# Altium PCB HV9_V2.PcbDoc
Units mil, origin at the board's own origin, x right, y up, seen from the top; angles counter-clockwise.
Board outline 6000 x 4000 mil, 2 copper layers (顶面, 底面), stack 12.7 mil thick; 1 components, 0 nets, 72 pads, 0 vias.
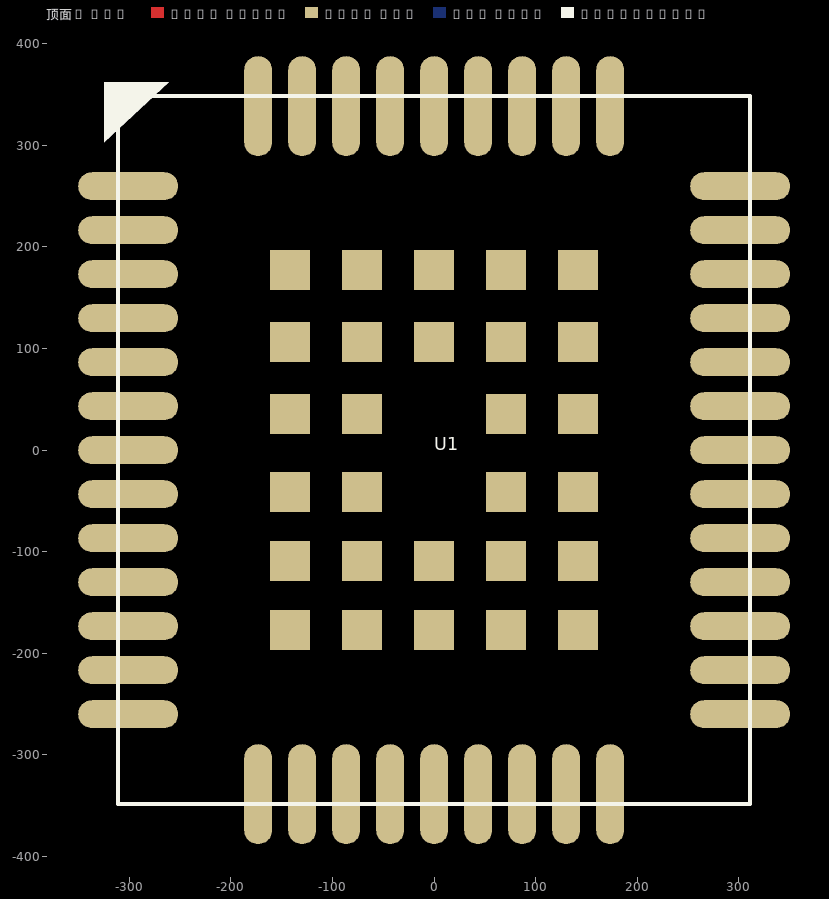
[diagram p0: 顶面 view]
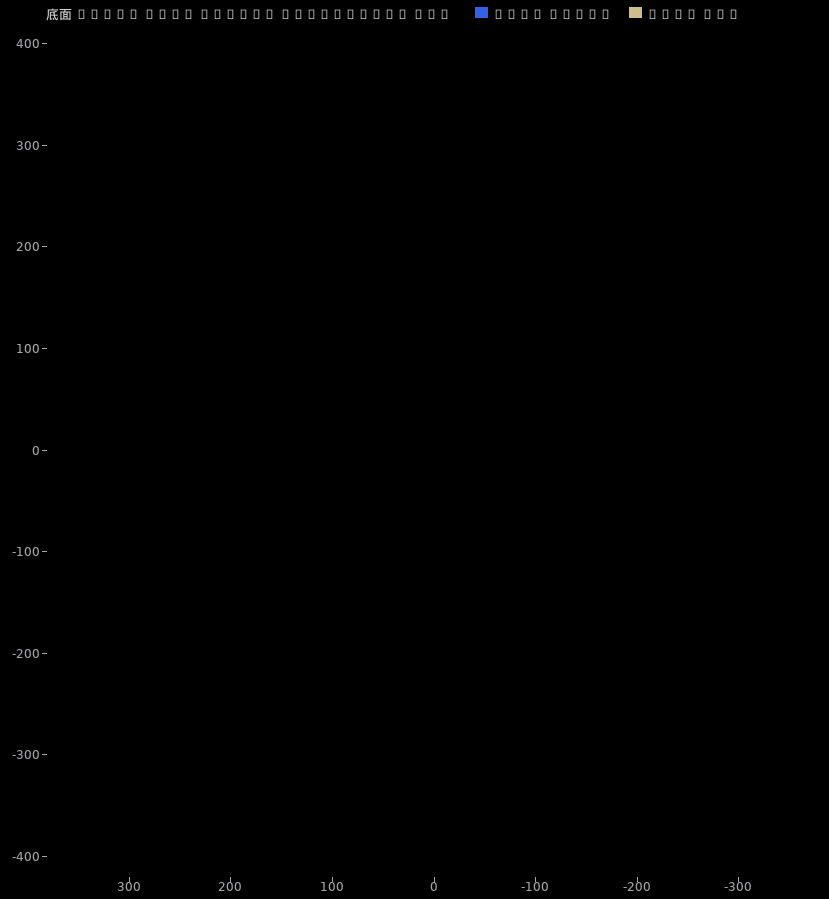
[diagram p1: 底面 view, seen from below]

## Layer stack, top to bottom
Top Solder: solder mask 0.4, Solder Resist, Dk 3.5
顶面: signal copper 1.35
Dielectric 1: dielectric 10, FR-4, Dk 4.3
底面: signal copper 1.35
Bottom Solder: solder mask 0.4, Solder Resist, Dk 3.5

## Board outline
-9000,-9000 -3000,-9000 -3000,-5000 -9000,-5000

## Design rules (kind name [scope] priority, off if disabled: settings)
Clearance "Clearance - Default - DEFAULT- SMD" [IsVia vs IsSMTPin] p1: gap=6
Clearance "Clearance - Default - DEFAULT - Via" [IsVia vs IsVia] p2: gap=6
Clearance "Clearance - Default - DEFAULT - Net" [All] p3: gap=6 except(10: Text-Text)
ComponentClearance "ComponentClearance - Default - DEFAULT" [All] p1: gap=6 collisioncheckmode=3 verticalgap=10 showdistances=FALSE
FanoutControl Fanout_Small [(CompPinCount < 5)] p3: bgadir=Out bgaviamode=Centered fanoutstyle=Auto fanoutdirection=OutThenIn viagrid=1 // Fanout_Small (Default Rule)
FanoutControl Fanout_SOIC [IsSOIC] p4: bgadir=Out bgaviamode=Centered fanoutstyle=Auto fanoutdirection=Alternating viagrid=1 // Fanout_SOIC (Default Rule)
HoleToHoleClearance "HoleToHoleClearance - Default - DEFAULT" [All] p1: gap=6 allowstackedmicrovias=TRUE
Length "Default Length" [All] p1: maxlimit=50000 minlimit=0
MaxMinImpedance "Default Impedance" [All] p1: minimum=50.00 maximum=150.0
ParallelSegment "Default Parallel Segment Adjasent" [All] p1: limit=1000 gap=200
ParallelSegment "Default Parallel Segment Same Layer" [All] p2: limit=1000 gap=200
PlaneConnect "Default PlaneConnect" [All] p1: planeconnectstyle=Relief reliefexpansion=20 reliefentries=0 reliefconductorwidth=15 reliefairgap=10
PolygonConnect "PolygonConnect - Default SMT" [IsSMTPin] p1: connectstyle=Relief reliefconductorwidth=10 reliefentries=4 polygonreliefangle="45 Angle" airgapwidth=10
PolygonConnect "PolygonConnect - Default Pad" [All] p2: connectstyle=Relief reliefconductorwidth=15 reliefentries=4 polygonreliefangle="45 Angle" airgapwidth=10
RoutingLayers "RoutingLayers - Default - DEFAULT" [All] p1: top layer_v5=TRUE bottom layer_v5=TRUE
RoutingPriority "RoutingPriority - Default - DEFAULT" [All] p1: routingpriority=3
RoutingTopology "Default Routing Topology" [All] p1: topology=Shortest
RoutingVias "RoutingVias - Default - DEFAULT" [All] p1: holewidth=37 width=55 viastyle="Through Hole" minholewidth=37 minwidth=55 maxholewidth=37 maxwidth=55
SMDToCorner "SMDToCorner - Default - DEFAULT" [All] p1: distance=60000
SolderMaskExpansion [All] p1: expansion=4
Width "Default Width" [All] p1: maxlimit=6 minlimit=6 preferedwidth=6
22 further rules are at their usual default settings.

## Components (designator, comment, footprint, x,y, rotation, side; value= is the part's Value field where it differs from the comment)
U1 "HV9_V2" HV9_V2 0,0 r0 top

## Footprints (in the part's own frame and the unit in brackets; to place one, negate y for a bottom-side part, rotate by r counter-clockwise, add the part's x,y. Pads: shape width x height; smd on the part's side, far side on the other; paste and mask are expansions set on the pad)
HV9_V2 [mm]
  oval 2.5x0.7 smd mask+0.05: 1(-7.65,6.6) 2(-7.65,5.5) 3(-7.65,4.4) 4(-7.65,3.3) 5(-7.65,2.2) 6(-7.65,1.1) 7(-7.65,0) 8(-7.65,-1.1) 9(-7.65,-2.2) 10(-7.65,-3.3) 11(-7.65,-4.4) 12(-7.65,-5.5) 13(-7.65,-6.6) 23(7.65,-6.6) 24(7.65,-5.5) 25(7.65,-4.4) 26(7.65,-3.3) 27(7.65,-2.2) 28(7.65,-1.1) 29(7.65,0) 30(7.65,1.1) 31(7.65,2.2) 32(7.65,3.3) 33(7.65,4.4) 34(7.65,5.5) 35(7.65,6.6)
  oval 0.7x2.5 smd mask+0.05: 14(-4.4,-8.6) 15(-3.3,-8.6) 16(-2.2,-8.6) 17(-1.1,-8.6) 18(0,-8.6) 19(1.1,-8.6) 20(2.2,-8.6) 21(3.3,-8.6) 22(4.4,-8.6) 36(4.4,8.6) 37(3.3,8.6) 38(2.2,8.6) 39(1.1,8.6) 40(0,8.6) 41(-1.1,8.6) 42(-2.2,8.6) 43(-3.3,8.6) 44(-4.4,8.6)
  rect 1x1 smd mask+0.05: 45(-3.6,4.5) 46(-3.6,2.7) 47(-3.6,0.9) 48(-3.6,-1.05) 49(-3.6,-2.77) 50(-3.6,-4.5) 51(-1.8,-4.5) 52(0,-4.5) 53(1.8,-4.5) 54(3.6,-4.5) 55(3.6,-2.77) 56(3.6,-1.05) 57(3.6,0.9) 58(3.6,2.7) 59(3.6,4.5) 60(1.8,4.5) 61(0,4.5) 62(-1.8,4.5) 63(-1.8,2.7) 64(-1.8,0.9) 65(-1.8,-1.05) 66(-1.8,-2.77) 67(0,-2.77) 68(1.8,-2.77) 69(1.8,-1.05) 70(1.8,0.9) 71(1.8,2.7) 72(0,2.7)
  silkscreen extent -8.25,-8.85 7.9,9.2

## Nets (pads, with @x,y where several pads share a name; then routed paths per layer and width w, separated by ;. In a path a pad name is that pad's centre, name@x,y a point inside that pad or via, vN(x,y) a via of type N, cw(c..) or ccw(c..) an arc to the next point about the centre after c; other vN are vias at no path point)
pads on no net: U1.1 U1.2 U1.3 U1.4 U1.5 U1.6 U1.7 U1.8 U1.9 U1.10 U1.11 U1.12 U1.13 U1.14 U1.15 U1.16 U1.17 U1.18 U1.19 U1.20 U1.21 U1.22 U1.23 U1.24 U1.25 U1.26 U1.27 U1.28 U1.29 U1.30 U1.31 U1.32 U1.33 U1.34 U1.35 U1.36 U1.37 U1.38 U1.39 U1.40 U1.41 U1.42 U1.43 U1.44 U1.45 U1.46 U1.47 U1.48 U1.49 U1.50 U1.51 U1.52 U1.53 U1.54 U1.55 U1.56 U1.57 U1.58 U1.59 U1.60 U1.61 U1.62 U1.63 U1.64 U1.65 U1.66 U1.67 U1.68 U1.69 U1.70 U1.71 U1.72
